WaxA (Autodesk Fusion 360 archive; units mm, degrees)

design "Wax Part A" references "HappyRing v7 Wax Mold Negative B", "HappyRing v7 v8_Part A Top"
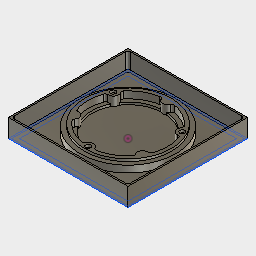
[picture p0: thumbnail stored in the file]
component_insert "Component Insert1"
component_insert "Component Insert2"

design "HappyRing v7 v8_Part A Top"
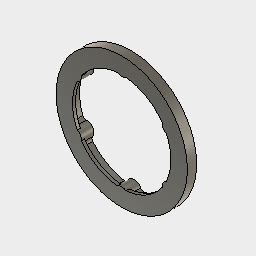
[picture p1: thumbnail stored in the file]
base_feature "Base Feature" bodies "Part A Top"
named bodies: "Part A Top"

design "HappyRing v7 Wax Mold Negative B"
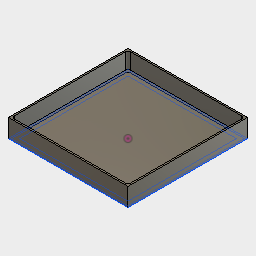
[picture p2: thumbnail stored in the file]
parameter "height" = 23 comment "height of the component"
parameter "rail_height" = 3
parameter "exrtusion_delta_for_magnets" = 0.8
parameter "diameter" = 130
parameter "inner_diameter" = 110
parameter "diameter_offet" = 10
parameter "pressfit_offset" = 1
parameter "magnet_diameter" = 6.4
parameter "magnet_height" = 3.2
parameter "holes_position_from_diameter" = 20
parameter "plateform_height" = 5.75 (= "height / 4")
parameter "plateform_inner_diameter" = 100
parameter "tool_diameter" = 3
sketch "base" plane through (0, 0, 0) normal (0, 1, 0) x axis (1, 0, 0)
  line L1 (68, -68) -> (-68, -68)
  line L2 (68, 68) -> (68, -68)
  line L3 (-68, 68) -> (68, 68)
  line L4 (-68, -68) -> (-68, 68)
  line L5 (-73, 73) -> (73, 73)
  line L6 (-73, -73) -> (-73, 73)
  line L7 (73, -73) -> (-73, -73)
  line L8 (73, 73) -> (73, -73)
  line L9 (75, 75) -> (75, -75)
  line L10 (-75, 75) -> (75, 75)
  line L11 (-75, -75) -> (-75, 75)
  line L12 (75, -75) -> (-75, -75)
  point P2 (-68, -68)
  point P3 (68, -68)
  point P5 (-68, 68)
  point P1 (0, 0)
  dimension "d138" distance P2 P3 = 136 (= "diameter + 2 * tool_diameter")
  dimension "d139" distance P2 P5 = 136 (= "diameter + 2 * tool_diameter")
  dimension "d143" = 5
  dimension "d144" = 7
  dimension "d152" distance P1 L9 = 75
  dimension "d153" distance P1 L10 = 75
extrude "Extrude20" new body sketch "base" profile of L5 L7 L6 L8 L9 L10 L12 L11 along normal blind 23 (= "height")
extrude "Extrude21" new body sketch "base" profile of L1 L2 L3 L4 along normal blind 5
extrude "Extrude22" add sketch "base" profile of L1 L2 L3 L4 L5 L7 L6 L8 along normal blind 3 (= "rail_height")
fillet "Fillet4" radius 3 (= "tool_diameter")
